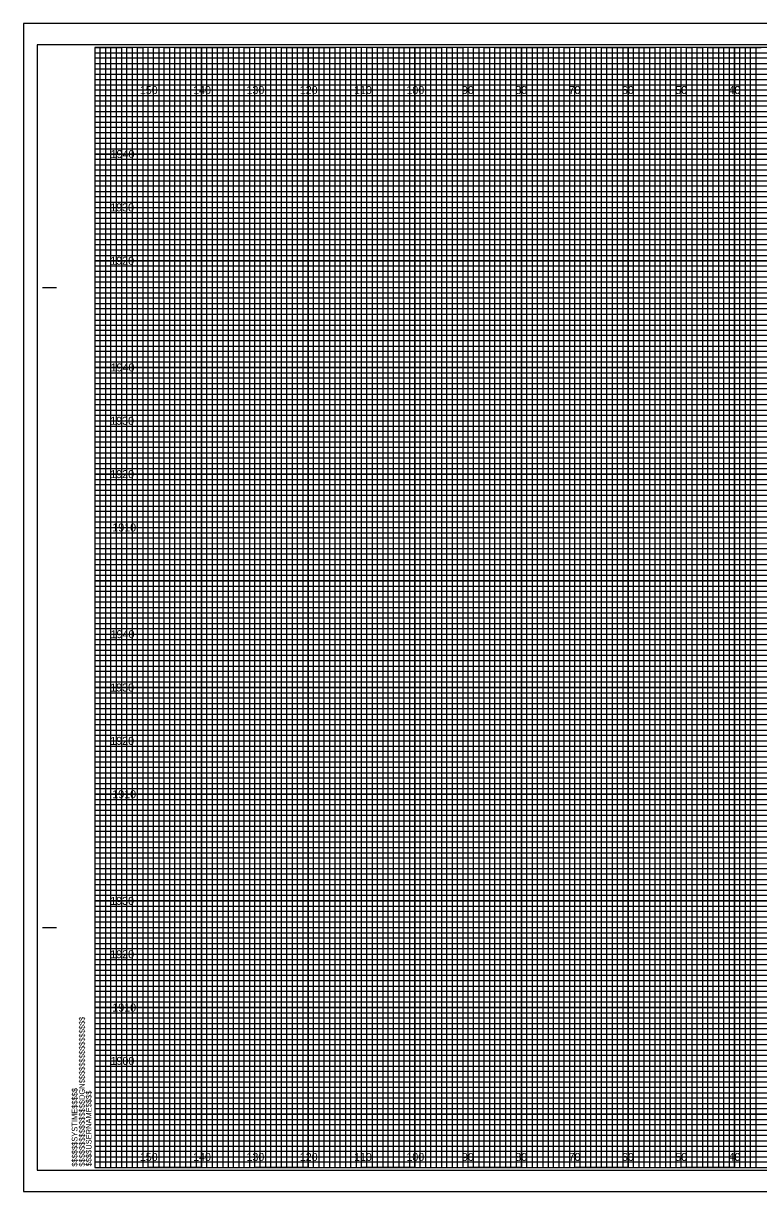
# Model space of a CAD drawing. Extents: x -13 to 323, y -4 to 214.
# Drawn here: x -13.4 to 124.5, y -4.5 to 214.5 of the extents above; entities that cross this region are included whole.
import ezdxf

# ---------------------------------------------------------------- set-up
doc = ezdxf.new("R2010")
doc.units = 0
for name, color, linetype in [('Prop XS Elevation Labels', 7, 'Continuous'), ('Prop XS Offset Labels', 7, 'Continuous'), ('Sheet Cross Section CELL', 7, 'Continuous'), ('Sheet Cross Section Grid Major CELL', 7, 'Continuous'), ('Sheet Cross Section Grid Middle CELL', 7, 'Continuous'), ('Sheet Cross Section Grid Minor 1 CELL', 7, 'Continuous'), ('Sheet Cross Section Grid Minor 2 CELL', 7, 'Continuous'), ('Sheet Cutting Line CELL', 7, 'Continuous'), ('Sheet DOT Grid CELL', 7, 'Continuous'), ('Sheet Plot Border Inside CELL', 7, 'Continuous'), ('Sheet Plot Border Outside CELL', 7, 'Continuous')]:
    doc.layers.add(name, color=color, linetype=linetype)

msp = doc.modelspace()

# ---------------------------------------------------------------- linework, layer by layer
at = {"layer": 'Sheet Cross Section CELL'}
for p, q in [((-9.8, 165), (-7.3, 165)), ((-9.7, 165), (-7.2, 165)), ((-9.8, 45), (-7.3, 45)), ((-9.7, 45), (-7.2, 45))]:
    msp.add_line(p, q, dxfattribs=at)
msp.add_lwpolyline([(320, 210), (0, 210), (0, 0), (320, 0)], close=True, dxfattribs=at)
at = {"layer": 'Sheet Cross Section Grid Major CELL'}
for p, q in [((10, 210), (0, 210)), ((10, 0), (10, 210)), ((30, 210), (20, 210)), ((20, 210), (20, 0)), ((30, 0), (30, 210)), ((50, 210), (40, 210)), ((40, 210), (40, 0)), ((50, 0), (50, 210)), ((70, 210), (60, 210)), ((60, 210), (60, 0)), ((70, 0), (70, 210)), ((90, 210), (80, 210)), ((80, 210), (80, 0)), ((90, 0), (90, 210)), ((110, 210), (100, 210)), ((100, 210), (100, 0)), ((110, 0), (110, 210)), ((130, 210), (120, 210)), ((120, 210), (120, 0)), ((20, 0), (10, 0)), ((40, 0), (30, 0)), ((60, 0), (50, 0)), ((80, 0), (70, 0)), ((100, 0), (90, 0)), ((120, 0), (110, 0))]:
    msp.add_line(p, q, dxfattribs=at)
for points in [[(0, 200), (320, 200), (320, 190), (0, 190)], [(0, 180), (320, 180), (320, 170), (0, 170)], [(0, 160), (320, 160), (320, 150), (0, 150)], [(0, 140), (320, 140), (320, 130), (0, 130)], [(0, 120), (320, 120), (320, 110), (0, 110)], [(0, 100), (320, 100), (320, 90), (0, 90)], [(0, 80), (320, 80), (320, 70), (0, 70)], [(0, 60), (320, 60), (320, 50), (0, 50)], [(0, 40), (320, 40), (320, 30), (0, 30)], [(0, 20), (320, 20), (320, 10), (0, 10)]]:
    msp.add_lwpolyline(points, dxfattribs=at)
at = {"layer": 'Sheet Cross Section Grid Middle CELL'}
for points in [[(0, 210), (5, 210), (5, 0), (15, 0), (15, 210), (25, 210), (25, 0), (35, 0), (35, 210), (45, 210), (45, 0), (55, 0), (55, 210), (65, 210), (65, 0), (75, 0), (75, 210), (85, 210), (85, 0), (95, 0), (95, 210), (105, 210), (105, 0), (115, 0), (115, 210), (125, 210)], [(0, 205), (275, 205)], [(0, 185), (320, 185), (320, 195), (0, 195)], [(0, 165), (320, 165), (320, 175), (0, 175)], [(0, 145), (320, 145), (320, 155), (0, 155)], [(0, 125), (320, 125), (320, 135), (0, 135)], [(0, 105), (320, 105), (320, 115), (0, 115)], [(0, 85), (320, 85), (320, 95), (0, 95)], [(0, 65), (320, 65), (320, 75), (0, 75)], [(0, 45), (320, 45), (320, 55), (0, 55)], [(0, 25), (320, 25), (320, 35), (0, 35)], [(0, 5), (320, 5), (320, 15), (0, 15)]]:
    msp.add_lwpolyline(points, dxfattribs=at)
at = {"layer": 'Sheet Cross Section Grid Minor 1 CELL'}
for p, q in [((0, 209), (260, 209)), ((260, 207.98), (0, 207.98)), ((0, 207.98), (0, 207)), ((0, 207), (260, 207)), ((260, 205.89), (0, 205.89)), ((0, 205.89), (0, 204)), ((0, 204), (320, 204))]:
    msp.add_line(p, q, dxfattribs=at)
for points in [[(0, 203), (270, 203), (320, 203), (320, 202), (0, 202)], [(0, 201), (320, 201), (320, 199), (0, 199)], [(0, 198), (320, 198), (320, 197), (0, 196.98)], [(0, 196), (320, 196), (320, 194), (0, 194)], [(0, 193), (320, 193), (320, 192), (0, 192)], [(0, 191), (320, 191), (320, 189), (0, 189)], [(0, 188), (320, 188), (320, 187), (0, 187)], [(0, 186), (320, 186), (320, 184), (0, 184)], [(0, 183), (320, 183), (320, 182), (0, 182)], [(0, 181), (320, 181), (320, 179), (0, 179)], [(0, 178), (320, 178), (320, 177), (0, 177)], [(0, 176), (320, 176), (320, 173.95), (320, 173), (320, 172), (0, 172)], [(0, 174), (320, 174), (320, 173), (0, 173)], [(0, 171), (320, 171), (320, 169), (0, 169.03)], [(0, 169.03), (320, 169), (320, 168), (0, 168)], [(0, 167), (320, 167), (320, 166), (0, 166)], [(0, 164), (320, 164), (320, 163), (0, 163)], [(0, 162), (320, 162), (320, 161), (0, 161)], [(-0.07, 158.89), (320, 158.89), (320, 157.88), (-0.07, 157.88)], [(0, 157), (320, 157), (320, 156), (0, 156)], [(0, 154), (320, 154), (320, 153), (0, 153)], [(0, 152), (320, 152), (320, 151), (0, 151)], [(0, 149), (320, 149), (320, 148), (0, 148)], [(0, 147), (320, 147), (320, 146), (0, 146)], [(0, 144), (320, 144), (320, 143), (0, 143)], [(0, 142), (320, 142), (320, 141), (0, 141)], [(0, 139), (320, 139), (319.99, 137.98), (0, 138)], [(0, 137), (320, 137), (320, 136), (0, 136)], [(0, 134), (320, 134), (320, 133), (0, 133)], [(0, 132), (320, 132), (320, 131), (0, 131)], [(0, 129), (320, 129), (320, 128), (0, 128)], [(0, 127), (320, 127), (320, 126), (0, 126)], [(0, 124), (320, 124), (320, 123), (0, 123)], [(0, 122), (320, 122), (320, 121), (0, 121)], [(0, 119), (320, 119), (320, 118), (0, 118)], [(0, 116.99), (320.07, 116.91), (320, 116), (0, 116)], [(0, 114), (320, 114), (320, 113), (0, 113)], [(0, 112), (320, 112), (320, 111), (0, 111)], [(0, 109), (320, 109), (320, 108), (0, 108)], [(0, 107), (320, 107), (320, 106), (0, 106)], [(0, 104), (320, 104), (320, 103), (0, 103)], [(0, 102), (320, 102), (320, 101), (0, 101)], [(0, 99), (320, 99), (320, 98), (0, 98)], [(0, 97), (320, 97), (320, 96), (0, 96)], [(0, 94), (320, 94), (320, 93), (0, 93)], [(0, 92), (320, 92), (320, 91), (0, 91)], [(0, 89), (320, 89), (320, 88), (0, 88)], [(0, 87), (320, 87), (320, 86), (0, 86)], [(0, 84), (320, 84), (320, 83), (0, 83)], [(0, 82), (320, 82), (320, 81), (0, 81)], [(0, 79), (320, 79), (319.99, 77.98), (0, 78)], [(0, 77), (320, 77), (320, 76), (0, 76)], [(0, 74), (320, 74), (320, 73), (0, 73)], [(0, 72), (320, 72), (320, 71), (0, 71)], [(0, 69), (320, 69), (320, 68), (0, 68)], [(0, 67), (320, 67), (320, 66), (0, 66)], [(0, 64), (320, 64), (320, 63), (0, 63)], [(0, 62), (320, 62), (320, 61), (0, 61)], [(0, 59), (320, 59), (320, 58), (0, 58)], [(0, 56.99), (320.07, 56.91), (320, 56), (0, 56)], [(0, 54), (320, 54), (320, 53), (0, 53)], [(0, 52), (320, 52), (320, 51), (0, 51)], [(0, 49), (320, 49), (320, 48), (0, 48)], [(0, 47), (320, 47), (320, 46), (0, 46)], [(0, 44), (320, 44), (320, 43), (0, 43)], [(0, 42), (320, 42), (320, 41), (0, 41)], [(0, 39), (320, 39), (320, 38), (0, 38)], [(0, 37), (320, 37), (320, 36), (0, 36)], [(0, 34), (320, 34), (320, 33), (0, 33)], [(0, 32), (320, 32), (320, 31), (0, 31)], [(0, 29), (320, 29), (320, 28), (0, 28)], [(0, 27), (320, 27), (320, 26), (0, 26)], [(0, 24), (320, 24), (320, 23), (0, 23)], [(0, 22), (320, 22), (320, 21), (0, 21)], [(0, 19), (320, 19), (320, 18), (0, 18)], [(0, 17), (320, 17), (320, 16), (0, 16)], [(0, 14), (320, 14), (320, 13), (0, 13)], [(0, 12), (320, 12), (320, 11), (0, 11)], [(0, 9), (320, 9), (320, 8), (0, 8)], [(0, 7), (320, 7), (320, 6), (0, 6)], [(0, 4), (320, 4), (320, 3), (0, 3)], [(0, 2), (320, 2), (320, 1), (0, 1)]]:
    msp.add_lwpolyline(points, dxfattribs=at)
at = {"layer": 'Sheet Cross Section Grid Minor 2 CELL'}
for points in [[(0, 0), (1, 0), (1, 210), (2, 210), (2, 0)], [(2, 0), (3, 0), (3, 210), (4, 210), (4, 0)], [(5, 0), (6, 0), (6, 210), (7, 210), (7, 0)], [(7, 0), (8, 0), (8, 210), (9, 210), (9, 0)], [(10, 0), (11, 0), (11, 210), (12, 210), (12, 0)], [(12, 0), (13, 0), (13, 210), (14, 210), (14, 0)], [(15, 0), (16, 0), (16, 210), (17, 210), (17, 0)], [(17, 0), (18, 0), (18, 210), (19, 210), (19, 0)], [(20, 0), (21, 0), (21, 210), (22, 210), (22, 0)], [(22, 0), (23, 0), (23, 210), (24, 210), (24, 0)], [(25, 0), (26, 0), (26, 210), (27, 210), (27, 0)], [(27, 0), (28, 0), (28, 210), (29, 210), (29, 0)], [(30, 0), (31, 0), (31, 210), (32, 210), (32, 0)], [(32, 0), (33, 0), (33, 210), (34, 210), (34, 0)], [(35, 0), (36, 0), (36, 210), (37, 210), (37, 0)], [(37, 0), (38, 0), (38, 210), (39, 210), (39, 0)], [(40, 0), (41, 0), (41, 210), (42, 210), (42, 0)], [(42, 0), (43, 0), (43, 210), (44, 210), (44, 0)], [(45, 0), (46, 0), (46, 210), (47, 210), (47, 0)], [(47, 0), (48, 0), (48, 210), (49, 210), (49, 0)], [(50, 0), (51, 0), (51, 210), (52, 210), (52, 0)], [(52, 0), (53, 0), (53, 210), (54, 210), (54, 0)], [(55, 0), (56, 0), (56, 210), (57, 210), (57, 0)], [(57, 0), (58, 0), (58, 210), (59, 210), (59, 0)], [(60, 0), (61, 0), (61, 210), (62, 210), (62, 0)], [(62, 0), (63, 0), (63, 210), (64, 210), (64, 0)], [(65, 0), (66, 0), (66, 210), (67, 210), (67, 0)], [(67, 0), (68, 0), (68, 210), (69, 210), (69, 0)], [(70, 0), (71, 0), (71, 210), (72, 210), (72, 0)], [(72, 0), (73, 0), (73, 210), (74, 210), (74, 0)], [(75, 0), (76, 0), (76, 210), (77, 210), (77, 0)], [(77, 0), (78, 0), (78, 210), (79, 210), (79, 0)], [(80, 0), (81, 0), (81, 210), (82, 210), (82, 0)], [(82, 0), (83, 0), (83, 210), (84, 210), (84, 0)], [(85, 0), (86, 0), (86, 210), (87, 210), (87, 0)], [(87, 0), (88, 0), (88, 210), (89, 210), (89, 0)], [(90, 0), (91, 0), (91, 210), (92, 210), (92, 0)], [(92, 0), (93, 0), (93, 210), (94, 210), (94, 0)], [(95, 0), (96, 0), (96, 210), (97, 210), (97, 0)], [(97, 0), (98, 0), (98, 210), (99, 210), (99, 0)], [(100, 0), (101, 0), (101, 210), (102, 210), (102, 0)], [(102, 0), (103, 0), (103, 210), (104, 210), (104, 0)], [(105, 0), (106, 0), (106, 210), (107, 210), (107, 0)], [(107, 0), (108, 0), (108, 210), (109, 210), (109, 0)], [(110, 0), (111, 0), (111, 210), (112, 210), (112, 0)], [(112, 0), (113, 0), (113, 210), (114, 210), (114, 0)], [(115, 0), (116, 0), (116, 210), (117, 210), (117, 0)], [(117, 0), (118, 0), (118, 210), (119, 210), (119, 0)], [(120, 0), (121, 0), (121, 210), (122, 210), (122, 0)], [(122, 0), (123, 0), (123, 210), (124, 210), (124, 0)]]:
    msp.add_lwpolyline(points, dxfattribs=at)
at = {"layer": 'Sheet Cutting Line CELL'}
for p, q in [((323.3, 214.5), (-13.4, 214.5)), ((-13.4, 214.5), (-13.4, -4.5)), ((-13.4, -4.5), (323.3, -4.5))]:
    msp.add_line(p, q, dxfattribs=at)
at = {"layer": 'Sheet DOT Grid CELL'}
for p, q in [((10, 0), (10, 210)), ((20, 0), (20, 210)), ((30, 0), (30, 210)), ((40, 0), (40, 210)), ((50, 0), (50, 210)), ((60, 0), (60, 210)), ((70, 0), (70, 210)), ((80, 0), (80, 210)), ((90, 0), (90, 210)), ((100, 0), (100, 210)), ((110, 0), (110, 210)), ((120, 0), (120, 210)), ((0, 200), (320, 200)), ((0, 190), (320, 190)), ((0, 180), (320, 180)), ((0, 170), (320, 170)), ((0, 160), (320, 160)), ((0, 150), (320, 150)), ((0, 140), (320, 140)), ((0, 130), (320, 130)), ((0, 120), (320, 120)), ((0, 110), (320, 110)), ((0, 100), (320, 100)), ((0, 90), (320, 90)), ((0, 80), (320, 80)), ((0, 70), (320, 70)), ((0, 60), (320, 60)), ((0, 50), (320, 50)), ((0, 40), (320, 40)), ((0, 30), (320, 30)), ((0, 20), (320, 20)), ((0, 10), (320, 10))]:
    msp.add_line(p, q, dxfattribs=at)
at = {"layer": 'Sheet Plot Border Inside CELL'}
msp.add_lwpolyline([(-10.8, -0.5), (322.4, -0.5), (322.4, 210.5), (-10.8, 210.5)], close=True, dxfattribs=at)
at = {"layer": 'Sheet Plot Border Outside CELL'}
msp.add_lwpolyline([(-13.4, -4.5), (323.3, -4.5), (323.3, 214.5), (-13.4, 214.5)], close=True, dxfattribs=at)

# ---------------------------------------------------------------- texts
at = {"layer": 'Prop XS Elevation Labels'}
for s, p in [('1940', (2.97, 189.25)), ('1930', (2.89, 179.25)), ('1920', (2.9, 169.25)), ('1940', (2.97, 149.25)), ('1930', (2.89, 139.25)), ('1920', (2.9, 129.25)), ('1910', (3.28, 119.25)), ('1940', (2.97, 99.25)), ('1930', (2.89, 89.25)), ('1920', (2.9, 79.25)), ('1910', (3.28, 69.25)), ('1930', (2.89, 49.25)), ('1920', (2.9, 39.25)), ('1910', (3.28, 29.25)), ('1900', (2.95, 19.25))]:
    msp.add_text(s, height=1.5, dxfattribs=at).set_placement(p)
at = {"layer": 'Prop XS Offset Labels'}
for s, p in [('150', (8.44, 201.25)), ('140', (18.44, 201.25)), ('130', (28.44, 201.25)), ('120', (38.44, 201.25)), ('110', (48.62, 201.25)), ('100', (58.44, 201.25)), ('90', (68.86, 201.25)), ('80', (78.86, 201.25)), ('70', (88.86, 201.25)), ('60', (98.86, 201.25)), ('50', (108.86, 201.25)), ('40', (118.86, 201.25)), ('150', (8.44, 1.25)), ('140', (18.44, 1.25)), ('130', (28.44, 1.25)), ('120', (38.44, 1.25)), ('110', (48.62, 1.25)), ('100', (58.44, 1.25)), ('90', (68.86, 1.25)), ('80', (78.86, 1.25)), ('70', (88.86, 1.25)), ('60', (98.86, 1.25)), ('50', (108.86, 1.25)), ('40', (118.86, 1.25))]:
    msp.add_text(s, height=1.5, dxfattribs=at).set_placement(p)
at = {"layer": 'Sheet Cross Section CELL'}
for s, p in [('$$$$$$$$$$$$$$$$DGN$$$$$$$$$$$$$$$$', (-1.88, 0.18)), ('$$$$$$SYSTIME$$$$$', (-3.26, 0.18)), ('$$$$USERNAME$$$$', (-0.62, 0.23))]:
    msp.add_text(s, height=1.05, rotation=90, dxfattribs=at).set_placement(p)

doc.saveas('drawing.dxf')
